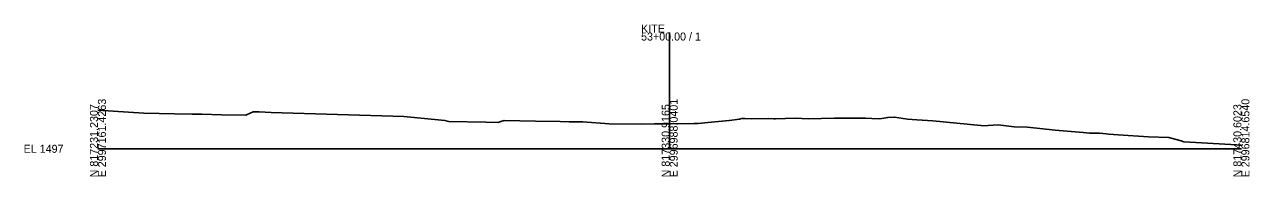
# Model space of a CAD drawing. Extents: x -26 to 2997147, y -10 to 817564.
# Drawn here: x -25.7 to 402.8, y 2990.3 to 3043.5 of the extents above; entities that cross this region are included whole.
import ezdxf

# ---------------------------------------------------------------- set-up
doc = ezdxf.new("R2010")
doc.units = 0
doc.layers.add('DESIGN - SHEET - Light Grid', color=7, linetype='Continuous')
doc.layers.add('SURVEY - GROUND - Top of Ground', color=7, linetype='Continuous')

msp = doc.modelspace()

# ---------------------------------------------------------------- linework, layer by layer
at = {"layer": 'DESIGN - SHEET - Light Grid'}
for p, q in [((200, 3000), (200, 3040.65)), ((0, 3000), (200, 3000)), ((200, 3000), (400, 3000))]:
    msp.add_line(p, q, dxfattribs=at)
at = {"layer": 'SURVEY - GROUND - Top of Ground'}
msp.add_lwpolyline([(0, 3013.55), (16.02, 3012.48), (26.74, 3012.27), (33, 3012.13), (36.36, 3012.08), (43.28, 3011.86), (51.71, 3011.76), (53.3, 3012.46), (54.26, 3012.87), (56.42, 3012.93), (60.54, 3012.65), (106.95, 3011.3), (119.01, 3010.14), (121.39, 3009.92), (122.26, 3009.6), (122.79, 3009.55), (135.67, 3009.29), (140.03, 3009.24), (140.97, 3009.49), (142.14, 3009.88), (153.06, 3009.68), (161.7, 3009.55), (164.87, 3009.4), (169.6, 3009.41), (178.83, 3008.75), (190.07, 3008.61), (194.67, 3008.68), (200.24, 3008.71), (208.62, 3008.81), (209.97, 3008.81), (213.38, 3009.17), (220.77, 3009.92), (224.48, 3010.33), (225.29, 3010.57), (226.26, 3010.54), (228.8, 3010.5), (234.52, 3010.53), (236.43, 3010.5), (237.02, 3010.51), (244.04, 3010.68), (248.4, 3010.52), (257.62, 3010.66), (268.47, 3010.71), (270.67, 3010.56), (273.54, 3010.49), (276.27, 3010.95), (278.71, 3011.08), (280.12, 3010.82), (283.17, 3010.38), (286.42, 3010.17), (292.06, 3009.8), (308.9, 3008.11), (309.69, 3008.08), (314.92, 3008.32), (320.52, 3007.71), (325.22, 3007.51), (334.88, 3006.51), (344.63, 3005.66), (345.68, 3005.55), (346.91, 3005.49), (350.34, 3005.48), (352.74, 3005.25), (353.67, 3005.15), (356.92, 3004.84), (367.47, 3004.21), (374.58, 3003.9), (375.86, 3003.62), (378.9, 3002.74), (379.86, 3002.48), (384.03, 3002.21), (398.32, 3001.33), (400, 3001.16)], dxfattribs=at)

# ---------------------------------------------------------------- texts
at = {"layer": 'DESIGN - SHEET - Light Grid'}
for s, p in [('KITE', (190, 3040.65)), ('53+00.00 / 1', (190, 3037.85)), ('EL 1497', (-26, 2998.6))]:
    msp.add_text(s, height=2.8, dxfattribs=at).set_placement(p)
for s, p in [('E 2997161.4263', (2.8, 2990)), ('E 2996988.0401', (202.8, 2990)), ('E 2996814.6540', (402.8, 2990)), ('N 817231.2307', (0, 2990)), ('N 817330.9165', (200, 2990)), ('N 817430.6023', (400, 2990))]:
    msp.add_text(s, height=2.8, rotation=90, dxfattribs=at).set_placement(p)

doc.saveas('drawing.dxf')
